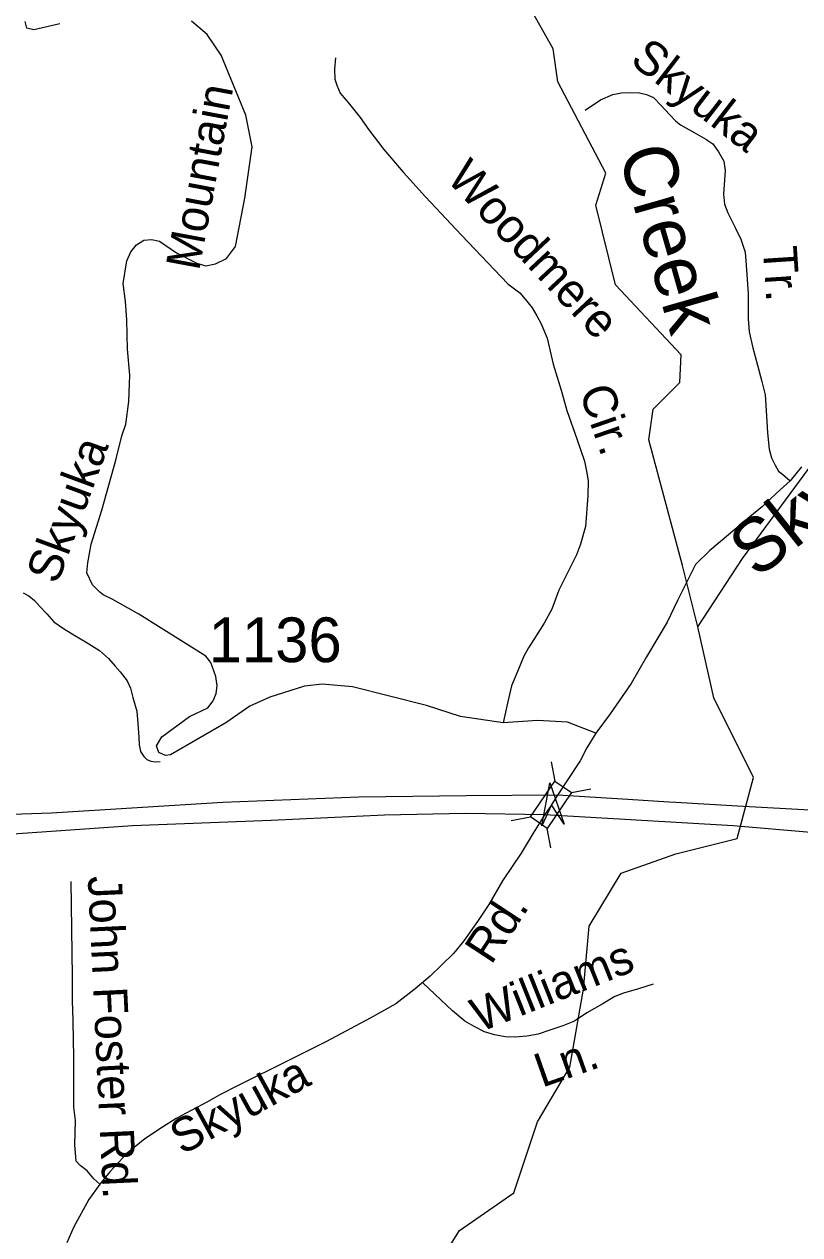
# Model space of a CAD drawing. Extents: x 990631 to 1056237, y 535999 to 585651.
# Drawn here: x 1035162 to 1037330, y 561861 to 565244 of the extents above; entities that cross this region are included whole.
import ezdxf

# ---------------------------------------------------------------- set-up
doc = ezdxf.new("R2010")
doc.units = 0
for name, color, linetype in [('Exist Hydrographic Creek Single Shore', 7, 'Continuous'), ('Exist Hydrographic Creek Single Shore Label', 7, 'Continuous'), ('Exist Road Non-System Type 51', 7, 'Continuous'), ('Exist Road Non-System Type 51 Label', 7, 'Continuous'), ('Exist Road Primary Interstate Divided Center Attributed', 7, 'Continuous'), ('Exist Road Secondary Structure Standard Bridge Attributed CELL', 7, 'Continuous'), ('Exist Road Secondary Structure Standard Bridge CELL', 7, 'Continuous'), ('Exist Road Secondary Type 51 Attributed', 7, 'Continuous'), ('Exist Road Secondary Type 51 Label', 7, 'Continuous'), ('Exist Road Secondary Type 51 Number Label', 7, 'Continuous')]:
    doc.layers.add(name, color=color, linetype=linetype)

msp = doc.modelspace()

# ---------------------------------------------------------------- linework, layer by layer
at = {"layer": 'Exist Hydrographic Creek Single Shore'}
for points in [[(1037044.6, 563559.5), (1037169.3, 563750.7), (1037368.1, 564019.8), (1037559.1, 564054.9), (1037753.3, 564272.7), (1037776.9, 564488.9), (1037621.7, 564843.2), (1037624, 564918.6), (1037863.8, 565117.3), (1038297.5, 565637), (1038320.6, 565836.7), (1038070.8, 566104.3), (1037992.3, 566256.9), (1037808.4, 567022), (1037738.6, 567180.9), (1037374.6, 567536.2), (1037272.5, 567731.9), (1037276.5, 567856.5), (1037246.9, 567972), (1036894.9, 568435.2)], [(1037044.6, 563559.5), (1037001.7, 563731.2), (1036908.1, 564082.2), (1036919.8, 564168), (1036993.9, 564242.1), (1036997.8, 564320.1), (1036814.6, 564515.1), (1036760, 564737.5), (1036787.3, 564827.2), (1036653.8, 565082.5), (1036640.1, 565174.8), (1036545.5, 565344), (1036187.2, 565613.8), (1036034.6, 565794.1), (1035795.7, 566143.5), (1035726.2, 566322.2), (1035575.2, 566551.7), (1035349.5, 566792.5), (1035062.6, 566952.6), (1034884.1, 567097.3), (1034685.1, 567396.6), (1034385.6, 567681.7)], [(1036140.8, 561607.7), (1036287.6, 561727.9), (1036312.4, 561767.6), (1036378.6, 561872.9), (1036530.7, 561978.2), (1036596.9, 562177.1), (1036686.6, 562329.2), (1036725.6, 562547.6), (1036741.2, 562723.2), (1036830.8, 562871.4), (1036982.9, 562926), (1037154.4, 562968.9), (1037200.1, 563138.5), (1037089.8, 563361.2), (1037044.6, 563559.5)]]:
    msp.add_lwpolyline(points, dxfattribs=at)
at = {"layer": 'Exist Road Non-System Type 51'}
for points in [[(1036032, 565149.5), (1036029, 565117.8), (1036030, 565089.6), (1036035.5, 565073.4), (1036044.8, 565051.3), (1036067.9, 565024.4), (1036100.7, 564983.3), (1036125.6, 564948.4), (1036167.7, 564893.1), (1036221.8, 564829.4), (1036283.7, 564761.3), (1036384.2, 564654.1), (1036514.1, 564517.8), (1036547.2, 564492.7), (1036566.5, 564469.9), (1036582, 564451.4), (1036595.1, 564429.2), (1036606.5, 564406.7), (1036623.3, 564366.2), (1036640.8, 564293.6), (1036662.5, 564220.7), (1036678.8, 564164.2), (1036706.2, 564085.2), (1036728.2, 564022.5), (1036733.4, 563994.4), (1036738.5, 563968.1), (1036737.2, 563926.1), (1036730.3, 563840.4), (1036716.7, 563790.7), (1036705.9, 563761.1), (1036686.6, 563723.7), (1036673.8, 563698.1), (1036656.7, 563662.6), (1036636.8, 563609.2), (1036615.6, 563569.8), (1036586.1, 563524.8), (1036571.4, 563501.3), (1036558.6, 563477.5), (1036543.4, 563442), (1036523.9, 563394.6), (1036512.5, 563347), (1036505.4, 563313.1), (1036500.6, 563291.4)], [(1036729.7, 565003.1), (1036772.7, 565031.8), (1036807.2, 565046.7), (1036831.3, 565052), (1036855.3, 565053.2), (1036881.3, 565052.2), (1036901.2, 565047.6), (1036920.9, 565039), (1036942.2, 565016.4), (1036965.5, 564991.5), (1036983, 564973), (1036996.6, 564962.5), (1037034, 564941.3), (1037067.4, 564922.3), (1037086.9, 564909.7), (1037102.3, 564887.1), (1037117.4, 564860.6), (1037120.6, 564834.5), (1037116.5, 564768.6), (1037119.5, 564740.5), (1037128.7, 564716.1), (1037149.4, 564675.5), (1037164.4, 564643), (1037177.3, 564606.5), (1037180.1, 564570.5), (1037185.5, 564490.1), (1037185.3, 564420.1), (1037188.2, 564384), (1037198.7, 564339.6), (1037211.1, 564291.3), (1037223.6, 564244.9), (1037232.5, 564208.5), (1037235.2, 564164.4), (1037239.2, 564102.3), (1037243.6, 564056), (1037250.9, 564031.8), (1037260.3, 564011.4), (1037269.8, 563995.2), (1037281.4, 563986.8), (1037302.9, 563968.2)], [(1035159.5, 563654.5), (1035175.1, 563646), (1035190.8, 563633.5), (1035206.3, 563617), (1035225.5, 563596.4), (1035244.9, 563573.8), (1035272.3, 563554.8), (1035303.7, 563535.8), (1035335.1, 563516.9), (1035372.5, 563493.6), (1035397.6, 563470.9), (1035417, 563450.3), (1035430.5, 563433.8), (1035449.8, 563409), (1035459, 563388.8), (1035466.3, 563362.4), (1035477.1, 563324.2), (1035480, 563289.9), (1035482.7, 563251.9), (1035484, 563229.8), (1035487.5, 563211.8), (1035497, 563197.4), (1035504.8, 563189.2), (1035516.5, 563184.8), (1035528.5, 563182.3), (1035542.5, 563184)], [(1036919.5, 562561.3), (1036879.2, 562548.7), (1036836.7, 562536), (1036812.3, 562526.9), (1036777.7, 562506), (1036734.8, 562481.2), (1036700.1, 562458.3), (1036667.6, 562445.3), (1036631.2, 562432.5), (1036598.7, 562421.5), (1036566.6, 562416.6), (1036534.6, 562413.6), (1036506.6, 562414.6), (1036476.7, 562419.6), (1036449, 562428.3), (1036419.3, 562443.3), (1036393.8, 562458.1), (1036358.8, 562487.4), (1036277.2, 562564.6)]]:
    msp.add_lwpolyline(points, dxfattribs=at)
at = {"layer": 'Exist Road Primary Interstate Divided Center Attributed'}
for points in [[(1036652.4, 563089.6), (1036398.5, 563087.7), (1036097.3, 563084), (1035717, 563068.9), (1035238.8, 563038.8), (1034877.3, 563027.5), (1034470.7, 563034.2), (1034214.7, 563064.4), (1033921, 563132.2), (1033472.9, 563260.2), (1033194.3, 563354.4), (1032957.1, 563407.2), (1032603.2, 563475)], [(1032768.8, 563377.8), (1033070.1, 563321.3), (1033341.2, 563230.9), (1033762.9, 563102.8), (1034049, 563038.8), (1034222.2, 563008.6), (1034399.2, 562986), (1034613.8, 562967.2), (1034835.9, 562971), (1035144.7, 562982.3), (1035464.7, 563004.9), (1035852.5, 563019.9), (1036168.8, 563035), (1036394.7, 563038.8), (1036616.9, 563035.1)], [(1039600.5, 562674), (1039581.5, 562681.8), (1039260.3, 562773.6), (1039105.6, 562819.5), (1038966.3, 562855.2), (1038859.2, 562880.8), (1038745.4, 562902.9), (1038645.1, 562914.8), (1038408, 562926.1), (1038149.5, 562961), (1037990.1, 562982.4), (1037802.6, 563003.9), (1037599, 563028), (1037373.9, 563046.7), (1037155.6, 563058.8), (1036983.1, 563069), (1036964, 563070.2), (1036848.9, 563077.1), (1036652.4, 563089.6)], [(1036616.9, 563035.1), (1037143.5, 563005.2), (1037360.5, 562986.4), (1037616.4, 562958.3), (1037911.1, 562923.5), (1038670.6, 562818.9), (1038820.6, 562792.1), (1039040.2, 562743.9), (1039239.7, 562694.9)]]:
    msp.add_lwpolyline(points, dxfattribs=at)
at = {"layer": 'Exist Road Secondary Structure Standard Bridge Attributed CELL'}
msp.add_lwpolyline([(1036608.4, 563003.8), (1036630.9, 563123.7), (1036671.3, 563008.6), (1036635.5, 563062.9)], close=True, dxfattribs=at)
at = {"layer": 'Exist Road Secondary Structure Standard Bridge CELL'}
for p, q in [((1036645.7, 563128.3), (1036635.5, 563182.6)), ((1036691.2, 563097.2), (1036745.5, 563107.4)), ((1036523, 563018.5), (1036577.2, 563028.7)), ((1036634, 562942.6), (1036623.8, 562996.8))]:
    msp.add_line(p, q, dxfattribs=at)
msp.add_lwpolyline([(1036577.2, 563028.7), (1036645.4, 563128.5), (1036692.1, 563096.6), (1036623.8, 562996.8)], close=True, dxfattribs=at)
at = {"layer": 'Exist Road Secondary Type 51 Attributed'}
for points in [[(1035261.6, 565244.8), (1035188.9, 565228.2), (1035170.1, 565232.4), (1035165, 565251.2)], [(1035713.2, 565157.4), (1035674, 565215.1), (1035629.4, 565251.8)], [(1036759.9, 563263), (1036680.9, 563293.6), (1036597, 563298.3), (1036500.6, 563291.4), (1036381.1, 563309.2), (1036286.1, 563340.2), (1036080, 563392.5), (1035994.9, 563399.3), (1035945.6, 563394.2), (1035848.6, 563363.5), (1035792.4, 563338), (1035726.1, 563292), (1035571.3, 563201.8), (1035557.6, 563200.1), (1035538.9, 563208.6), (1035532.1, 563227.3), (1035547.4, 563252.9), (1035624, 563309), (1035675.6, 563333.8), (1035690.2, 563353.3), (1035698.8, 563373.2), (1035701.4, 563394.9), (1035698.3, 563421.2), (1035683.6, 563460.6), (1035669.9, 563477.6), (1035482.8, 563595.1), (1035408.3, 563636.7), (1035382.9, 563649.1), (1035373.9, 563656.3), (1035353.6, 563677), (1035337.5, 563711), (1035340.2, 563738.9), (1035349.9, 563790.5), (1035379, 563886.2), (1035418.1, 564025.8), (1035435.1, 564093.9), (1035446.6, 564125.7), (1035454.7, 564189.4), (1035457.2, 564263.4), (1035451.4, 564335.7), (1035448.8, 564417.4), (1035445.4, 564468.4), (1035438.5, 564519.5), (1035448.8, 564582.5), (1035460.7, 564608), (1035476, 564626.8), (1035496.4, 564640.4), (1035518.5, 564642.1), (1035540.6, 564637), (1035588.3, 564604.6), (1035644.4, 564575.7), (1035669.9, 564568.9), (1035697.2, 564574), (1035727.8, 564589.3), (1035752.9, 564622.2), (1035778.8, 564757.9), (1035799.7, 564900.5), (1035781.4, 564989.6), (1035713.2, 565157.4)], [(1037334.1, 564007.1), (1037302.9, 563968.2), (1037264.6, 563933.4), (1037225.7, 563895.6), (1037190.2, 563867), (1037130.6, 563816.6), (1037078, 563773), (1037037.9, 563734.1), (1036988.6, 563635.6), (1036958.9, 563572.5), (1036901.6, 563476.3), (1036858.1, 563401.8), (1036799.7, 563317.1), (1036759.9, 563263)], [(1036759.9, 563263), (1036734.5, 563221.7), (1036715.8, 563185.2), (1036679.2, 563130.7), (1036652.4, 563089.6)], [(1036652.4, 563089.6), (1036631.9, 563056.6), (1036616.9, 563035.1)], [(1036616.9, 563035.1), (1036584.7, 562983.3), (1036550.8, 562927), (1036499, 562850.2), (1036460.4, 562784.2), (1036430.9, 562739.2), (1036390.4, 562682.8), (1036361.7, 562647.4), (1036296.8, 562583.8), (1036254.7, 562548.3), (1036200.5, 562506.2), (1036129, 562466.7), (1036007.3, 562401.2), (1035899, 562347.6), (1035759.8, 562278.3), (1035708.8, 562251.9), (1035674.2, 562233), (1035629.3, 562208.5), (1035587.4, 562185.7), (1035548.6, 562161.7), (1035499.2, 562129.6), (1035449.7, 562089.4), (1035401.6, 562037.2), (1035373.8, 562002.6)], [(1035373.8, 562002.6), (1035357, 562017.1), (1035338.7, 562039.9), (1035318.6, 562054.6), (1035308, 562066.7), (1035303.9, 562112.2), (1035305.3, 562180.4), (1035301.3, 562217.9), (1035301.3, 562362.4), (1035299.9, 562402.5), (1035299.3, 562461.2), (1035297, 562515.3), (1035297.2, 562583.3), (1035293.8, 562848.7)], [(1035373.8, 562002.6), (1035342.7, 561959.6), (1035301.3, 561883.4), (1035281.2, 561839.2)]]:
    msp.add_lwpolyline(points, dxfattribs=at)

# ---------------------------------------------------------------- texts
at = {"layer": 'Exist Hydrographic Creek Single Shore Label'}
for s, rotation, p in [('Creek', 286.0317, (1036822.1, 564884.2)), ('Skyuka', 38.4062, (1037209.9, 563691.9))]:
    msp.add_text(s, height=150, rotation=rotation, dxfattribs=at).set_placement(p)
at = {"layer": 'Exist Road Non-System Type 51 Label'}
for s, rotation, p in [('Skyuka', 322.3777, (1036851.7, 565136.3)), ('Woodmere', 313.13, (1036339.2, 564810)), ('Tr.', 273.8357, (1037226.1, 564620.9)), ('Cir.', 289.1463, (1036712.1, 564218.3)), ('Williams', 21.7457, (1036435.1, 562426)), ('Ln.', 19.4406, (1036609.2, 562271.8))]:
    msp.add_text(s, height=95, rotation=rotation, dxfattribs=at).set_placement(p)
at = {"layer": 'Exist Road Secondary Type 51 Label'}
for s, rotation, p in [('Mountain', 79.4214, (1035651, 564552.4)), ('Skyuka', 69.7375, (1035255.1, 563675.9)), ('John Foster Rd.', 272.73, (1035340, 562862.5)), ('Rd.', 56.7532, (1036467.3, 562613.1)), ('Skyuka', 28.622, (1035603.5, 562083))]:
    msp.add_text(s, height=95, rotation=rotation, dxfattribs=at).set_placement(p)
at = {"layer": 'Exist Road Secondary Type 51 Number Label'}
msp.add_text('1136', height=125, dxfattribs=at).set_placement((1035677.7, 563461.1))

doc.saveas('drawing.dxf')
